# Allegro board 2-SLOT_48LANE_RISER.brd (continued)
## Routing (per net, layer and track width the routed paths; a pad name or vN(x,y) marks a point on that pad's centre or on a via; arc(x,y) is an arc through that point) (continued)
PE_CPU_RX_C_DN<12>: length 182
  TOP w0.089: 118.42,92.03 118.44,92.03 118.5,91.97 118.98,91.97 119.18,91.77 121.59,91.77 121.97,92.15 123.08,92.15 v5(123.29,92.36)
  TOP w0.135: 118.42,92.03 117.52,92.03 117.37,92.18 116.68,92.18 116.53,92.03 115.2,92.03 114.94,91.99 110.15,88.63 107.12,84.3 107.12,71.91 106.55,68.71 104.72,66.09 104.72,62.04 104.89,61.07 105.98,59.51 107.55,58.41 113.89,57.3 v8(120.37,50.82) 122.9,48.29 139.75,48.29 168.47,43.22 203.84,18.46 219.36,15.72 219.46,15.57 220.05,15.47 220.2,15.57 220.73,15.48 220.84,15.32 221.41,15.22 221.57,15.33 221.94,15.26 222.28,15.03 222.62,14.97 222.77,14.76 223.19,14.69 223.4,14.83 223.72,14.77 223.86,14.57 224.28,14.5 224.48,14.64 224.74,14.59 224.85,14.44 225.35,14.35 225.5,14.46 225.74,14.42 226.07,14.19 226.16,13.68 226.03,13.54 226.03,13.04 226.16,12.9 226.16,12.68 C99.1
  BOTTOM w0.135: U1.AB19 v5(123.29,92.36)
PE_CPU_RX_C_DN<13>: length 181.4
  TOP w0.089: v5(123.29,93.16) 123.05,92.93 121.78,92.93 121.63,92.78 120.09,92.78 119.65,93.22 119.01,93.22 118.95,93.28 118.93,93.28
  TOP w0.135: C100.1 222.17,12.69 222.17,12.88 221.99,13.06 221.99,13.25 222.18,13.43 222.18,13.62 221.97,13.78 221.28,13.9 221.12,13.78 220.59,13.88 220.47,14.04 219.94,14.14 219.79,14.03 219.24,14.12 219.13,14.28 218.79,14.34 218.4,14.61 217.01,14.86 216.86,14.75 216.29,14.85 216.19,15 215.66,15.09 215.48,14.97 214.95,15.06 214.83,15.24 214.3,15.33 214.17,15.24 213.56,15.35 213.47,15.48 203.19,17.29 167.98,41.95 139.1,47.04 v8(130,47.04) 122.15,47.04 114.93,54.26 112.01,56.31 106.74,57.23 104.87,58.55 103.78,60.09 103.52,61.61 103.52,67.03 105.41,69.73 105.92,72.62 105.92,84.6 106.05,85.28 108.73,89.11 114.69,93.28 118.93,93.28
  BOTTOM w0.124: U1.AB20 v5(123.29,93.16)
PE_CPU_RX_C_DN<14>: length 181.5
  TOP w0.089: 119.04,94.25 119.06,94.25 119.12,94.19 120.34,94.19 120.67,94.53 123.65,94.53 123.72,94.46 124.01,94.46 124.09,94.53 v5(124.09,94.76)
  TOP w0.135: 119.04,94.25 118.4,94.25 117.96,94.69 114.61,94.69 107.81,89.93 104.76,85.57 104.71,85.41 104.71,72.98 104.24,70.31 102.11,67.26 102.11,61.91 102.47,59.88 104.14,57.49 106.08,56.13 111.54,55.17 112.46,54.52 112.46,54.52 113.39,53.87 v8(119.79,47.47) 121.44,45.82 138.78,45.82 167.49,40.76 202.71,16.1 212.78,14.33 212.87,14.2 217.21,13.43 217.34,13.52 217.84,13.43 218.13,13.14 218.16,12.95 218.16,12.68 C101.1
  BOTTOM w0.135: U1.AB22 v5(124.09,94.76)
PE_CPU_RX_C_DN<15>: length 181.6
  TOP w0.089: v5(123.29,95.56) 123.51,95.56 123.59,95.47 123.59,95.22 123.49,95.12 119.94,95.12 119.48,95.57 119.48,95.65 119.47,95.67
  TOP w0.135: C102.1 214.15,11.91 214.15,12.3 213.77,12.56 211.75,12.92 211.54,13.23 202.2,14.87 166.86,39.61 139.42,44.45 121.01,44.45 v8(114.73,50.72) 112.78,52.68 110.78,54.08 105.38,55.03 102.94,56.74 101.1,59.37 100.91,60.44 100.91,67.69 103.05,70.75 103.51,73.36 103.51,86.07 103.56,86.13 106.9,90.89 114.1,95.93 114.41,95.99 119.15,95.99 119.47,95.67
  BOTTOM w0.135: U1.AB23 v5(123.29,95.56)
PE_CPU_RX_C_DP<0>: length 179.5
  TOP w0.089: 122.82,75.31 122.82,75.34 122.76,75.39 122.76,75.77 123.73,76.73 123.73,77.07 123.81,77.16 v5(124.09,77.16)
  TOP w0.135: C23.1 278.49,12.69 278.49,14.16 277.17,16.1 268.63,22.08 212.26,32.02 207.5,35.35 206.71,36.48 177.03,57.27 132.76,65.07 130.23,65.07 v8(125.86,69.44) 122.82,72.48 122.82,72.92 122.96,73.06 122.96,73.6 122.82,73.74 122.82,75.31 122.82,75.31
  BOTTOM w0.135: U1.AA1 v5(124.09,77.16)
PE_CPU_RX_C_DP<1>: length 179.7
  TOP w0.089: v5(124.09,77.96) 124.07,77.96 123.38,77.55 121.82,77.55 121.42,77.95 121.02,77.95 120.71,77.64 120.71,77.2
  TOP w0.135: C24.1 273.48,12.69 273.48,13.36 272.23,14.61 261.61,22.05 211.84,30.83 206.39,34.64 205.65,35.7 176.45,56.15 134.34,63.58 132.83,63.58 132.65,63.75 132.11,63.75 131.93,63.58 131.4,63.58 131.22,63.75 130.68,63.75 130.5,63.58 129.95,63.58 v8(122.39,71.13) 121.6,71.92 121.6,74.7 120.71,75.59 120.71,77.2
  BOTTOM w0.135: U1.AA2 v5(124.09,77.96)
PE_CPU_RX_C_DP<2>: length 179.3
  TOP w0.089: 120.3,78.73 120.32,78.74 120.32,78.82 120.67,79.17 123.53,79.17 v5(124.09,79.56)
  TOP w0.135: 120.3,78.73 120.3,78.65 119.69,78.03 119.69,75.21 119.99,74.9 119.99,71.81 v8(124.26,67.54) 129.67,62.13 130.3,62.13 130.43,62.26 131.02,62.26 131.14,62.13 131.68,62.13 131.78,62.23 132.42,62.23 132.53,62.13 135.09,62.13 175.64,54.98 204.77,34.61 205.35,33.78 211.14,29.72 257.3,21.59 257.42,21.54 257.42,21.54 262.47,19.44 268.47,15.24 269.43,13.87 269.48,13.59 269.48,12.69 C25.1
  BOTTOM w0.135: U1.AA4 v5(124.09,79.56)
PE_CPU_RX_C_DP<3>: length 178.6
  TOP w0.089: v5(124.09,80.36) 123.54,79.98 121,79.98 120.98,79.96
  TOP w0.135: 120.98,79.96 120.14,79.96 118.64,78.45 118.64,71.31 119.75,70.2 119.9,70.2 120.36,69.74 120.36,69.59 120.74,69.21 120.85,69.21 121.35,68.71 121.35,68.6 v8(122.03,67.92) 123.26,66.69 125.28,64.67 129.22,60.73 130.58,60.73 130.7,60.86 131.29,60.86 131.42,60.73 131.96,60.73 132.09,60.86 132.68,60.86 132.8,60.73 136.09,60.73 174.9,53.89 204.1,33.47 204.49,32.92 210.67,28.59 210.67,28.59 255.58,20.66 259.21,18.12 261.45,16.56 261.45,16.56 265.34,13.83 265.46,13.67 265.46,12.72 C26.1
  BOTTOM w0.135: U1.AA5 v5(124.09,80.36)
PE_CPU_RX_C_DP<4>: length 177.8
  TOP w0.089: v5(124.09,81.96) 123.55,81.58 121.39,81.58 120.96,82.01 120.38,82.01 120.32,81.95 120.3,81.95
  TOP w0.135: C79.1 259.46,12.71 259.46,14.05 258.27,15.76 255.64,17.59 247.91,20.8 210.2,27.44 173.92,52.84 136.65,59.41 133.25,59.41 133.15,59.51 132.51,59.51 132.41,59.41 131.87,59.41 131.8,59.49 131.11,59.49 131.03,59.41 128.66,59.41 v8(124.11,63.96) 121.29,66.78 121.29,66.93 120.91,67.31 120.76,67.31 120.22,67.85 120.22,67.96 120.22,68.03 119.81,68.44 119.73,68.44 119.63,68.44 119.25,68.82 119.25,69 118.85,69.4 118.77,69.4 118.67,69.4 117.44,70.63 117.44,79.66 118.38,80.99 119.62,81.86 120.16,81.95 120.3,81.95
  BOTTOM w0.135: U1.AA7 v5(124.09,81.96)
PE_CPU_RX_C_DP<5>: length 177.8
  TOP w0.089: 119.72,82.74 119.74,82.74 119.79,82.79 121.35,82.79 121.76,82.38 123.55,82.38 v5(124.09,82.76)
  TOP w0.135: C80.1 255.47,12.7 255.47,14.73 254.66,15.55 250.63,18.37 247.59,19.63 209.73,26.31 173.45,51.7 137.15,58.1 131.04,58.1 130.93,58.21 130.29,58.21 130.18,58.1 129.64,58.1 129.53,58.21 128.9,58.21 128.79,58.1 128.03,58.1 v8(120.69,65.44) 118.79,67.34 118.79,67.52 118.39,67.92 118.21,67.92 117.83,68.31 117.83,68.48 117.42,68.89 117.24,68.89 116.23,69.9 116.23,79.89 116.29,80.19 116.49,80.49 117.53,81.97 118.47,82.63 119.09,82.74 119.72,82.74
  BOTTOM w0.135: U1.AA8 v5(124.09,82.76)
PE_CPU_RX_C_DP<6>: length 177.7
  TOP w0.089: v5(124.09,84.36) 123.7,84.09 123.24,83.94 122.04,83.94 121.92,83.81 121.36,83.81 121.16,84.02 119.42,84.02 119.36,83.97
  TOP w0.135: C81.1 251.53,12.65 251.53,12.85 251.36,13.78 251.36,13.79 251.08,15.38 250.52,16.18 247.25,18.47 209.13,25.19 172.91,50.58 137.16,56.88 127.33,56.88 123.81,60.41 v8(122.23,61.99) 118.22,66 118.22,66.11 118.22,66.19 117.81,66.59 117.62,66.59 117.24,66.98 117.24,67.16 116.83,67.57 116.65,67.57 116.27,67.95 116.27,68.12 115.84,68.55 115.67,68.55 115.03,69.18 115.03,80.51 116.49,82.59 116.65,82.82 118.22,83.91 118.37,83.94 118.36,83.94 118.51,83.97 119.36,83.97
  BOTTOM w0.135: U1.AA10 v5(124.09,84.36)
PE_CPU_RX_C_DP<7>: length 177.5
  TOP w0.089: 118.88,85.14 118.9,85.14 118.96,85.19 120.04,85.19 120.49,84.75 123.28,84.75 123.29,84.76 123.39,84.79 123.66,84.91 124.08,85.16 v5(124.09,85.16)
  TOP w0.135: 118.88,85.14 117.75,85.14 117.25,85.05 116.49,84.52 115.5,83.82 113.89,81.52 113.83,81.22 113.83,68.33 114.42,67.75 114.58,67.75 115.01,67.31 115.01,67.15 115.39,66.77 115.55,66.77 115.98,66.34 115.98,66.18 v8(119.52,62.64) 126.63,55.53 127.92,55.53 127.99,55.61 127.99,55.61 128.07,55.68 128.6,55.68 128.68,55.61 128.68,55.61 128.75,55.53 129.29,55.53 129.36,55.61 129.36,55.61 129.44,55.68 129.98,55.68 130.05,55.61 130.05,55.61 130.12,55.53 137.68,55.53 172.45,49.4 208.67,24.05 239.69,18.58 244.52,16.58 247.04,14.81 247.47,14.19 247.47,12.7 C82.1
  BOTTOM w0.135: U1.AA11 v5(124.09,85.16)
PE_CPU_RX_C_DP<8>: length 176.8
  TOP w0.089: 118.42,86.34 118.44,86.34 118.5,86.39 118.88,86.39 119.43,86.94 123.21,86.94 v5(124.09,87.56)
  TOP w0.135: 118.42,86.34 117.08,86.34 116.61,86.14 116.49,86.06 114.7,84.8 112.63,81.85 112.63,67.78 115.4,65.01 115.4,64.61 116.18,63.84 116.28,63.84 116.78,63.33 116.78,63.23 117.17,62.85 117.29,62.85 117.77,62.36 117.77,62.24 v8(120.78,59.23) 125.81,54.2 127.87,54.2 128,54.33 128.64,54.33 128.77,54.2 129.31,54.2 129.44,54.33 130.08,54.33 130.21,54.2 138.32,54.2 171.98,48.27 208.2,22.91 236.56,17.91 239.57,16.66 242.24,14.8 242.47,14.14 242.47,12.7 C83.1
  BOTTOM w0.135: U1.AA13 v5(124.09,87.56)
PE_CPU_RX_C_DP<9>: length 176.8
  TOP w0.089: v5(124.09,88.36) 123.51,87.96 122.29,87.96 122.05,87.72 118.96,87.72 118.93,87.69
  TOP w0.135: 118.93,87.69 117.52,87.69 116.49,87.51 116.31,87.47 113.91,85.79 112.5,84.38 111.5,82.95 111.43,82.55 111.43,67.28 113.59,65.12 113.59,64.49 114.33,63.75 114.53,63.75 114.96,63.32 114.96,63.12 115.34,62.74 115.55,62.74 115.98,62.3 115.98,62.1 116.36,61.72 116.56,61.72 117,61.29 117,61.08 v8(117.9,60.19) 125.3,52.78 139.44,52.78 171.4,47.15 207.61,21.8 235.88,16.81 237.32,15.8 238.48,14.14 238.48,12.69 C84.1
  BOTTOM w0.135: U1.AA14 v5(124.09,88.36)
PE_CPU_RX_C_DP<10>: length 180.1
  TOP w0.089: v5(124.09,89.96) 123.69,89.56 122.97,89.56 122.62,89.2 119.69,89.2 119.43,88.95 118.88,88.95 118.82,88.89 118.8,88.89
  TOP w0.135: 118.8,88.89 116.87,88.89 116.49,88.83 115.95,88.73 112.95,86.63 111.09,84.77 110.73,84.26 110.23,83.05 110.23,66.78 112.19,64.82 112.19,63.63 112.89,62.93 113.04,62.93 113.47,62.5 113.47,62.35 113.85,61.97 114,61.97 114.44,61.54 114.44,61.38 v8(119.6,56.22) 124.44,51.38 125.67,51.38 125.79,51.51 126.38,51.51 126.51,51.38 127.05,51.38 127.15,51.49 127.79,51.49 127.89,51.38 140.44,51.38 170.72,46.05 173.81,43.88 173.95,43.13 174.18,42.97 174.93,43.1 175.37,42.79 175.5,42.04 175.73,41.88 176.48,42.01 176.92,41.7 177.05,40.95 177.28,40.79 178.03,40.92 178.47,40.61 178.6,39.87 178.84,39.7 179.59,39.84 180.03,39.53 180.16,38.78 180.39,38.62 181.14,38.75 182.25,37.97 182.35,37.38 182.94,36.97 183.53,37.07 184.33,36.52 184.43,35.93 185.02,35.51 185.61,35.62 206.93,20.69 227.12,17.13 230.69,16.5 231.22,16.13 233.29,15.77 233.89,15.35 234.47,14.52 234.47,12.7 C85.1
  BOTTOM w0.135: U1.AA16 v5(124.09,89.96)
PE_CPU_RX_C_DP<11>: length 182.4
  TOP w0.089: v5(124.09,90.76) 123.69,90.36 122.89,90.36 122.53,90.01 119.88,90.01 119.46,90.42 118.93,90.42 118.87,90.37 118.85,90.37
  TOP w0.135: 118.85,90.37 118.85,90.37 116.5,90.37 116.49,90.37 115.93,90.27 110.89,86.74 109.69,85.02 109.69,85.02 108.62,83.08 108.62,71.31 108.03,67.97 106.22,65.39 106.22,62.31 106.26,62.11 106.94,61.14 108.65,59.95 109.67,59.76 109.83,59.88 110.36,59.78 110.48,59.62 111.91,59.37 112.05,59.47 112.62,59.37 112.72,59.23 114.67,58.88 115.92,57.64 116.1,57.64 116.51,57.23 116.51,57.05 v8(118.28,55.28) 123.57,49.99 128.67,49.99 128.82,50.14 129.36,50.14 129.52,49.99 130.31,49.99 130.47,50.14 131.01,50.14 131.16,49.99 140.29,49.99 169.23,44.88 184.69,34.06 205.05,19.8 224.16,16.41 226.67,15.96 227.15,15.63 227.63,15.29 229.9,15.29 230.51,14.68 230.51,12.67 C86.1
  BOTTOM w0.135: U1.AA17 v5(124.09,90.76)
PE_CPU_RX_C_DP<12>: length 182.2
  TOP w0.089: 118.42,91.73 118.44,91.73 118.5,91.78 118.9,91.78 119.1,91.58 121.67,91.58 122.05,91.96 123.69,91.96 v5(124.09,92.36)
  TOP w0.135: C87.1 226.47,12.7 226.47,13.7 226.35,14.36 225.86,14.7 222.4,15.32 222.06,15.55 203.96,18.74 168.59,43.51 139.77,48.59 126.18,48.59 126,48.77 125.54,48.77 125.36,48.59 124.89,48.59 124.72,48.77 124.25,48.77 124.07,48.59 123.03,48.59 v8(119.47,52.15) 116.73,54.89 116.73,55.13 116.35,55.51 116.11,55.51 115.73,55.89 115.73,56.13 115.35,56.51 115.11,56.51 114.04,57.58 107.67,58.7 106.2,59.73 105.18,61.19 105.02,62.07 105.02,65.99 106.84,68.59 107.42,71.88 107.42,84.2 110.37,88.41 115.06,91.7 115.22,91.73 118.42,91.73
  BOTTOM w0.135: U1.AA19 v5(124.09,92.36)
PE_CPU_RX_C_DP<13>: length 181.5
  TOP w0.089: 118.93,92.97 118.95,92.97 119.01,93.03 119.57,93.03 120.01,92.59 121.71,92.59 121.86,92.74 123.66,92.74 v5(124.09,93.16)
  TOP w0.135: C88.1 222.48,12.69 222.48,13.77 222.09,14.07 218.91,14.63 218.52,14.9 203.31,17.58 168.21,42.16 168.1,42.24 139.13,47.35 v8(127.79,47.35) 122.28,47.35 121.49,48.13 121.49,48.26 120.98,48.77 120.86,48.77 120.26,49.36 120.26,49.47 120.26,49.56 119.86,49.97 119.65,49.97 118.86,50.76 118.86,50.94 118.45,51.35 118.27,51.35 117.05,52.58 117.05,52.69 117.05,52.78 116.64,53.18 116.44,53.18 115.13,54.49 112.13,56.59 106.86,57.52 105.08,58.77 104.07,60.21 103.82,61.63 103.82,66.93 105.69,69.61 106.22,72.59 106.22,84.48 106.34,85.16 108.95,88.89 114.78,92.97 118.93,92.97
  BOTTOM w0.135: U1.AA20 v5(124.09,93.16)
PE_CPU_RX_C_DP<14>: length 181.4
  TOP w0.089: v5(124.09,93.96) 124.09,94.17 123.99,94.27 123.64,94.27 123.57,94.34 120.75,94.34 120.42,94 119.12,94 119.06,93.94 119.04,93.94
  TOP w0.135: 119.04,93.94 118.28,93.94 117.83,94.39 114.71,94.39 108.03,89.71 105.05,85.45 105.02,85.28 105.02,72.95 104.53,70.19 102.41,67.17 102.41,61.93 102.76,60 104.36,57.71 106.2,56.42 111.66,55.46 113.1,54.45 113.58,54.11 113.6,54.09 114.64,53.05 114.74,53.05 114.84,53.05 115.22,52.67 115.22,52.57 115.22,52.47 115.6,52.09 115.78,52.09 116.19,51.68 116.19,51.51 116.57,51.13 116.75,51.13 117.15,50.72 117.15,50.54 117.57,50.13 117.67,50.13 118.18,49.62 118.18,49.52 v8(118.81,48.88) 121.57,46.13 138.81,46.13 167.61,41.05 202.83,16.39 212.95,14.6 213.05,14.47 217.13,13.75 217.26,13.84 217.98,13.72 218.41,13.29 218.47,12.98 218.47,12.71 C89.1
  BOTTOM w0.135: U1.AA22 v5(124.09,93.96)
PE_CPU_RX_C_DP<15>: length 181.7
  TOP w0.089: v5(124.09,95.56) 123.87,95.56 123.78,95.47 123.78,95.14 123.57,94.93 119.86,94.93 119.35,95.44 119.27,95.44 119.25,95.45
  TOP w0.135: C90.1 214.45,11.96 214.45,12.46 213.89,12.85 211.93,13.2 211.71,13.5 202.32,15.16 166.98,39.9 139.44,44.75 128,44.75 127.9,44.86 127.06,44.86 126.96,44.75 126.42,44.75 126.32,44.86 125.47,44.86 125.37,44.75 124.83,44.75 124.73,44.86 123.89,44.86 123.79,44.75 123.25,44.75 123.12,44.88 122.33,44.88 122.2,44.75 121.13,44.75 v8(114,51.89) 112.97,52.92 110.9,54.37 105.5,55.32 103.16,56.96 101.38,59.49 101.21,60.46 101.21,67.59 103.34,70.63 103.82,73.33 103.82,85.96 103.82,85.96 107.12,90.67 114.22,95.64 114.44,95.68 119.02,95.68 119.25,95.45
  BOTTOM w0.135: U1.AA23 124.49,95.16 v5(124.09,95.56)
PE_CPU_RX_DN<0>: length 8.3
  TOP w0.135: C35.2 278.17,11.18 278.17,6.15 277.83,5.8 J5.A17
PE_CPU_RX_DN<1>: length 8.3
  TOP w0.135: C36.2 273.17,11.18 273.17,6.15 272.83,5.8 J5.A22
PE_CPU_RX_DN<2>: length 8.3
  TOP w0.135: J5.A26 268.83,5.8 269.19,6.16 269.19,11.17 C37.2
PE_CPU_RX_DN<3>: length 8.3
  TOP w0.135: C38.2 265.17,11.18 265.17,6.15 264.83,5.8 J5.A30
PE_CPU_RX_DN<4>: length 8.3
  TOP w0.135: C91.2 259.17,11.18 259.17,6.15 258.83,5.8 J5.A36
PE_CPU_RX_DN<5>: length 8.3
  TOP w0.135: C92.2 255.17,11.18 255.17,6.15 254.83,5.8 J5.A40
PE_CPU_RX_DN<6>: length 8.4
  TOP w0.135: C93.2 251.17,11.18 251.17,10.1 251.06,9.98 251.06,9.39 251.17,9.28 251.17,6.15 250.83,5.8 J5.A44
PE_CPU_RX_DN<7>: length 8.3
  TOP w0.135: C94.2 247.17,11.18 247.17,6.15 246.83,5.8 J5.A48
PE_CPU_RX_DN<8>: length 8.3
  TOP w0.135: C95.2 242.17,11.18 242.17,6.15 241.83,5.8 J5.A53
PE_CPU_RX_DN<9>: length 8.3
  TOP w0.135: J5.A57 237.83,5.8 238.17,6.15 238.17,11.18 C96.2
PE_CPU_RX_DN<10>: length 8.3
  TOP w0.135: J5.A61 233.83,5.8 234.17,6.15 234.17,11.18 C97.2
PE_CPU_RX_DN<11>: length 8.3
  TOP w0.135: C98.2 230.17,11.18 230.17,6.15 229.83,5.8 J5.A65
PE_CPU_RX_DN<12>: length 8.3
  TOP w0.135: J5.A69 225.83,5.8 226.17,6.15 226.17,11.18 C99.2
PE_CPU_RX_DN<13>: length 8.3
  TOP w0.135: J5.A73 221.83,5.8 222.17,6.15 222.17,11.18 C100.2
PE_CPU_RX_DN<14>: length 8.3
  TOP w0.135: C101.2 218.17,11.18 218.17,6.15 217.83,5.8 J5.A77
PE_CPU_RX_DN<15>: length 7.5
  TOP w0.135: J5.A81 213.83,5.8 214.17,6.15 214.17,10.42 C102.2
PE_CPU_RX_DP<0>: length 8.3
  TOP w0.135: C23.2 278.48,11.18 278.48,6.15 278.83,5.8 J5.A16
PE_CPU_RX_DP<1>: length 8.3
  TOP w0.135: C24.2 273.48,11.18 273.48,6.15 273.83,5.8 J5.A21
PE_CPU_RX_DP<2>: length 8.4
  TOP w0.135: C25.2 269.5,11.2 269.5,8.5 269.65,8.35 269.65,7.81 269.5,7.66 269.5,6.13 269.83,5.8 J5.A25
PE_CPU_RX_DP<3>: length 8.3
  TOP w0.135: C26.2 265.48,11.18 265.48,6.15 265.83,5.8 J5.A29
PE_CPU_RX_DP<4>: length 8.3
  TOP w0.135: C79.2 259.48,11.18 259.48,6.15 259.83,5.8 J5.A35
PE_CPU_RX_DP<5>: length 8.3
  TOP w0.135: J5.A39 255.83,5.8 255.48,6.15 255.48,11.18 C80.2
PE_CPU_RX_DP<6>: length 8.3
  TOP w0.135: C81.2 251.48,11.18 251.48,6.15 251.83,5.8 J5.A43
PE_CPU_RX_DP<7>: length 8.3
  TOP w0.135: C82.2 247.48,11.18 247.48,6.15 247.83,5.8 J5.A47
PE_CPU_RX_DP<8>: length 8.3
  TOP w0.135: J5.A52 242.83,5.8 242.48,6.15 242.48,11.18 C83.2
PE_CPU_RX_DP<9>: length 8.3
  TOP w0.135: C84.2 238.48,11.18 238.48,6.15 238.83,5.8 J5.A56
PE_CPU_RX_DP<10>: length 8.3
  TOP w0.135: J5.A60 234.83,5.8 234.48,6.15 234.48,11.18 C85.2
PE_CPU_RX_DP<11>: length 8.3
  TOP w0.135: C86.2 230.48,11.18 230.48,6.15 230.83,5.8 J5.A64
PE_CPU_RX_DP<12>: length 8.3
  TOP w0.135: J5.A68 226.83,5.8 226.48,6.15 226.48,11.18 C87.2
PE_CPU_RX_DP<13>: length 8.3
  TOP w0.135: C88.2 222.48,11.18 222.48,6.15 222.83,5.8 J5.A72
PE_CPU_RX_DP<14>: length 8.3
  TOP w0.135: J5.A76 218.83,5.8 218.48,6.15 218.48,11.18 C89.2
PE_CPU_RX_DP<15>: length 7.5
  TOP w0.135: J5.A80 214.83,5.8 214.48,6.15 214.48,10.42 C90.2
PE_CPU_TX_DN<0>: length 190.5
  BOTTOM w0.135: J5.B15 279.83,5.8 280.17,6.15 280.17,9.3 279.31,14.21 277.99,15.52 277.37,15.96 277.35,15.96 277.29,16.01 277.27,16.03 269.22,21.67 269.17,21.68 212.14,31.73 209.71,33.43 207.28,35.13 203.4,40.68 181.2,56.22 139.18,63.63 v8(134.42,63.63) 130.25,63.63 122.52,71.36 122.52,74.78 121.61,75.69 121.61,77.24 U1.AE1
PE_CPU_TX_DN<1>: length 191.3
  BOTTOM w0.089: U1.AE2 121.11,78.18 120.98,78.18 120.52,77.72 120.52,77.31 120.43,77.22 120.42,77.22 120.41,77.21 120.41,77.2
  BOTTOM w0.135: 120.41,77.2 120.41,75.47 121.3,74.58 121.3,73.9 121.16,73.76 121.16,73.22 121.3,73.08 121.3,70.87 129.68,62.48 129.7,62.48 129.75,62.43 v8(130.46,62.43) 138.65,62.43 180.81,55 202.31,39.95 206.16,34.45 211.68,30.58 212.1,30.47 260.45,21.94 264.14,19.36 264.58,19.44 265,20.05 265.19,20.08 265.7,19.72 265.74,19.53 265.31,18.93 265.39,18.49 266.11,17.98 266.54,18.06 266.97,18.67 267.16,18.7 267.67,18.34 267.71,18.16 267.28,17.55 267.36,17.11 268.82,16.09 271.57,14.16 271.57,14.16 272.29,13.65 272.33,13.44 272.66,13.21 272.87,13.25 273.21,13.02 273.24,12.8 273.57,12.57 273.79,12.61 274.4,12.18 275,11.33 275.17,10.33 275.17,6.15 274.83,5.8 J5.B20
PE_CPU_TX_DN<2>: length 187.6
  BOTTOM w0.089: 120.03,79.05 120.12,79.15 120.13,79.15 120.59,79.61 120.77,79.79 121.11,79.79 U1.AE4 ; 119.21,77.5 119.21,77.47
  BOTTOM w0.135: J5.B24 270.83,5.8 271.17,6.15 271.17,10.24 271,11.22 270.45,12 269.95,12.35 269.74,12.32 269.41,12.55 269.37,12.76 269.04,12.99 268.83,12.96 268.5,13.19 268.46,13.4 257.18,21.3 211.02,29.44 205.13,33.56 201.09,39.33 180.34,53.84 139,61.13 v8(131.65,61.13) 129.23,61.13 120.3,70.05 119.69,70.67 119.69,72.84 119.53,72.99 119.53,73.53 119.69,73.69 119.69,74.78 119.21,75.26 119.21,77.47 ; 119.21,77.5 119.21,78.23 120.03,79.05
PE_CPU_TX_DN<3>: length 187.1
  BOTTOM w0.089: 120.12,80.64 120.14,80.64 120.2,80.58 121.11,80.58 U1.AE5
  BOTTOM w0.135: 120.12,80.64 119.88,80.64 119.44,80.56 118.47,79.88 118.33,79.19 118.33,70.2 128.6,59.93 v8(133.22,59.93) 138.89,59.93 179.87,52.7 200.23,38.46 204.27,32.7 210.55,28.3 254.05,20.62 264.26,13.48 264.3,13.26 264.63,13.03 264.84,13.07 265.18,12.84 265.21,12.62 265.54,12.39 265.76,12.43 266.36,12.01 267.01,11.08 267.17,10.14 267.17,6.15 266.83,5.8 J5.B28
PE_CPU_TX_DN<4>: length 184.9
  BOTTOM w0.089: 120.3,82.26 120.32,82.26 120.38,82.2 121.13,82.2 U1.AE7
  BOTTOM w0.135: 120.3,82.26 120.14,82.26 119.5,82.15 118.16,81.21 117.13,79.76 117.13,77.46 116.99,77.32 116.99,76.68 117.13,76.55 117.13,69.7 128.1,58.73 v8(129.21,58.73) 138.78,58.73 179.4,51.57 199.31,37.63 203.34,31.88 210.08,27.16 247.83,20.5 258.56,12.99 258.59,12.81 258.95,12.55 259.13,12.58 259.47,12.35 259.51,12.14 259.84,11.91 260.05,11.94 260.52,11.61 260.98,10.95 261.17,9.86 261.17,6.15 260.83,5.8 J5.B34
PE_CPU_TX_DN<5>: length 184.4
  BOTTOM w0.089: 119.72,83.04 119.74,83.04 119.79,82.98 121.11,82.98 U1.AE8
  BOTTOM w0.135: 119.72,83.04 119.04,83.04 119.03,83.04 118.35,82.92 117.31,82.19 116.49,81.02 116,80.31 115.93,79.91 115.93,69.2 127.6,57.53 v8(128.35,57.53) 138.68,57.53 158.81,53.98 178.93,50.43 198.45,36.77 202.47,31.02 209.61,26.02 244.75,19.82 252.15,14.64 254.62,12.91 254.65,12.7 254.99,12.47 255.2,12.51 255.53,12.27 255.57,12.06 255.9,11.83 256.11,11.87 256.44,11.64 256.98,10.87 257.17,9.76 257.17,6.15 256.83,5.8 J5.B38
PE_CPU_TX_DN<6>: length 184.2
  BOTTOM w0.089: 119.36,84.27 119.38,84.27 119.44,84.21 119.96,84.21 120.35,84.6 121.13,84.6 U1.AE10
  BOTTOM w0.135: J5.B42 252.83,5.8 253.17,6.15 253.17,9.86 253.01,10.77 252.46,11.56 251.97,11.9 251.76,11.87 251.43,12.1 251.39,12.31 251.06,12.54 250.85,12.5 250.51,12.74 250.48,12.95 241.62,19.15 209.02,24.9 201.67,30.07 197.59,35.9 178.46,49.29 138.57,56.32 v8(129.77,56.32) 127.11,56.32 114.73,68.7 114.73,80.6 116.43,83.04 116.49,83.08 118.1,84.2 118.49,84.27 119.36,84.27
PE_CPU_TX_DN<7>: length 184.1
  BOTTOM w0.089: U1.AE11 121.11,85.38 118.96,85.38 118.9,85.44 118.88,85.44
  BOTTOM w0.135: 118.88,85.44 117.7,85.44 117.7,85.44 117.13,85.34 116.49,84.89 115.28,84.04 113.6,81.64 113.53,81.24 113.53,68.2 126.61,55.12 v8(130.96,55.12) 138.26,55.12 178.05,48.11 196.72,35.04 200.84,29.16 208.55,23.76 238.78,18.43 246.53,13.01 246.57,12.79 246.9,12.56 247.11,12.6 247.44,12.37 247.48,12.15 247.81,11.92 248.03,11.96 248.61,11.55 249.06,10.91 249.17,10.27 249.17,6.15 248.83,5.8 J5.B46
PE_CPU_TX_DN<8>: length 183
  BOTTOM w0.089: 118.42,86.64 118.44,86.64 118.5,86.58 118.8,86.58 119.23,87.01 121.14,87.01 U1.AE13
  BOTTOM w0.135: 118.42,86.64 117.02,86.64 116.49,86.42 116.46,86.41 114.48,85.02 112.33,81.95 112.33,67.65 126.06,53.92 v8(129.14,53.92) 138.15,53.92 177.58,46.97 195.86,34.17 199.97,28.3 208.08,22.62 234.41,17.98 241.48,13.03 241.52,12.82 241.85,12.58 242.06,12.62 242.39,12.39 242.43,12.18 242.76,11.94 242.98,11.98 243.42,11.67 243.95,10.92 244.17,9.64 244.17,6.15 243.83,5.8 J5.B51
PE_CPU_TX_DN<9>: length 182.9
  BOTTOM w0.089: 118.93,87.99 118.95,87.99 119.01,87.93 119.46,87.93 119.61,87.78 121.11,87.78 U1.AE14
  BOTTOM w0.135: 118.93,87.99 117.49,87.99 116.49,87.82 116.19,87.76 113.72,86.03 112.26,84.58 111.21,83.07 111.12,82.57 111.12,67.16 125.56,52.72 v8(126.21,52.72) 138.03,52.72 177.11,45.83 195,33.31 199.11,27.44 207.61,21.49 231.31,17.31 234.05,15.39 236.78,13.48 236.82,13.27 237.15,13.03 237.37,13.07 237.7,12.84 237.73,12.63 238.07,12.39 238.28,12.43 238.61,12.2 238.65,11.99 238.98,11.76 239.19,11.79 239.64,11.48 239.85,11.18 240.06,10.87 240.17,10.25 240.17,6.15 239.83,5.8 J5.B55
PE_CPU_TX_DN<10>: length 186.7
  BOTTOM w0.089: 118.8,89.2 118.82,89.2 118.88,89.14 119.35,89.14 119.65,89.44 121.17,89.44 U1.AE16
  BOTTOM w0.135: J5.B59 235.83,5.8 236.17,6.15 236.17,9.6 235.95,10.86 235.38,11.67 234.48,12.3 234.27,12.27 233.94,12.5 233.9,12.71 233.57,12.94 233.36,12.91 233.03,13.14 232.99,13.35 231.82,14.17 231.56,14.12 231.45,13.96 230.94,13.87 230.51,14.17 230.42,14.68 230.54,14.84 230.49,15.1 230.27,15.25 230.01,15.21 229.9,15.05 229.39,14.96 228.96,15.26 228.87,15.77 228.98,15.93 228.94,16.19 228.33,16.61 207.13,20.35 198.25,26.57 194.14,32.44 176.64,44.69 137.95,51.51 v8(127.36,51.51) 125.07,51.51 115.74,60.84 115.61,60.84 115.48,60.84 115.2,60.56 114.68,60.56 114.31,60.92 114.31,61.44 114.59,61.72 114.59,61.99 114.4,62.18 114.14,62.18 113.86,61.9 113.34,61.9 112.97,62.27 112.97,62.78 113.25,63.06 113.25,63.33 109.92,66.66 109.92,83.11 110.46,84.41 110.85,84.97 112.75,86.86 115.83,89.02 116.49,89.14 116.85,89.2 118.8,89.2
PE_CPU_TX_DN<11>: length 188.2
  BOTTOM w0.089: U1.AE17 121.11,90.18 119.97,90.18 119.54,90.61 118.93,90.61 118.87,90.67
  BOTTOM w0.135: J5.B63 231.83,5.8 232.17,6.15 232.17,10.23 232.09,10.7 231.73,11.21 231.22,11.57 227.97,13.84 227.77,13.8 227.36,14.09 227.33,14.29 226.92,14.58 226.66,14.58 226.31,14.83 226.27,15.03 226.09,15.16 225.32,15.7 224.95,15.96 224.55,16.03 224.55,16.03 206.21,19.26 197.15,25.61 192.83,31.78 175.96,43.59 140.84,49.78 v8(128.5,49.78) 124.99,49.78 116.41,58.36 115.79,58.79 107.73,60.21 106.72,60.92 106.02,61.92 105.92,62.48 105.92,65.49 107.75,68.09 108.32,71.34 108.32,83.16 109.42,85.17 109.43,85.18 110.67,86.96 114.31,89.5 114.34,89.71 114.75,89.99 114.95,89.96 115.81,90.56 116.44,90.67 116.47,90.67 118.87,90.67 118.87,90.67
PE_CPU_TX_DN<12>: length 188.5
  BOTTOM w0.089: 118.42,92.03 118.44,92.03 118.5,91.97 118.98,91.97 119.24,91.71 121.04,91.71 U1.AE19
  BOTTOM w0.135: J5.B67 227.83,5.8 228.17,6.15 228.17,7.24 228.17,9.89 227.97,11.04 227.8,11.29 227.62,11.53 222.42,15.18 205.75,18.12 196.29,24.75 191.97,30.91 175.59,42.38 140.44,48.58 v8(127.28,48.58) 122.76,48.58 114.5,56.85 113.26,57.71 112.81,57.81 106.93,58.84 105.98,59.51 104.88,61.09 104.72,61.98 104.72,66.09 106.55,68.71 107.12,71.91 107.12,84.3 108.51,86.29 108.48,86.47 108.91,87.08 109.09,87.11 110.15,88.63 114.94,91.99 115.2,92.03 116.53,92.03 116.68,92.18 117.37,92.18 117.52,92.03 118.42,92.03
PE_CPU_TX_DN<13>: length 188.3
  BOTTOM w0.089: U1.AE20 121.11,92.58 119.94,92.58 119.3,93.22 119.01,93.22 118.95,93.28 118.93,93.28
  BOTTOM w0.135: J5.B71 223.83,5.8 224.17,6.15 224.17,9.92 224.11,10.27 224.05,10.62 223.42,11.51 219.2,14.47 205.39,16.91 195.08,24.12 190.76,30.29 175.11,41.25 140.33,47.38 v8(126.11,47.38) 122.26,47.38 116.35,53.3 116.12,53.3 115.67,53.75 115.67,53.97 114.38,55.26 112.68,56.46 106.49,57.55 105.1,58.52 103.71,60.5 103.52,61.61 103.52,67.03 105.41,69.73 105.92,72.62 105.92,84.6 106.05,85.28 108.73,89.11 114.69,93.28 115.75,93.28 115.82,93.35 115.89,93.42 116.54,93.42 116.61,93.35 116.68,93.28 118.93,93.28
PE_CPU_TX_DN<14>: length 188.5
  BOTTOM w0.089: U1.AE22 121.13,94.2 118.98,94.2 118.92,94.26 118.9,94.26
  BOTTOM w0.135: J5.B75 219.83,5.8 220.17,6.15 220.17,8.11 220.02,8.26 220.02,8.96 220.17,9.11 220.17,10.26 220.06,10.9 219.71,11.4 218.08,12.55 217.87,12.51 217.35,12.88 217.31,13.08 216.35,13.75 204.77,15.79 194.32,23.11 189.9,29.43 174.64,40.11 140.95,46.05 v8(125.3,46.05) 121.21,46.05 113.39,53.87 112.46,54.52 112.46,54.52 111.54,55.17 106.08,56.13 104.14,57.49 102.47,59.88 102.11,61.91 102.11,67.26 104.24,70.31 104.71,72.98 104.71,85.41 104.76,85.57 107.81,89.93 114.61,94.69 116,94.69 116.07,94.77 116.87,94.77 116.94,94.69 117.96,94.69 118.39,94.26 118.9,94.26
PE_CPU_TX_DN<15>: length 188.2
  BOTTOM w0.089: 119.47,95.67 119.48,95.65 119.48,95.57 120.07,94.98 121.11,94.98 U1.AE23
  BOTTOM w0.135: J5.B79 215.83,5.54 216.17,5.89 216.17,7.91 216.08,8 216.08,8.75 216.17,8.84 216.17,9.74 216.01,10.69 215.63,11.23 212.9,13.14 204.28,14.66 190.97,23.98 187.41,29.06 172.94,39.19 140.84,44.85 v8(122.2,44.85) 120.61,44.85 112.78,52.68 110.78,54.08 105.38,55.03 102.94,56.74 101.1,59.37 100.91,60.44 100.91,67.69 103.05,70.75 103.51,73.36 103.51,86.07 103.58,86.15 106.9,90.89 114.1,95.93 114.41,95.99 116.45,95.99 116.55,96.09 117.3,96.09 117.4,95.99 119.15,95.99 119.47,95.67
PE_CPU_TX_DP<0>: length 190.5
  BOTTOM w0.135: J5.B14 280.83,5.8 280.48,6.15 280.48,9.33 279.59,14.35 278.19,15.76 277.47,16.26 277.44,16.28 277.07,16.54 276.64,16.85 276.55,16.9 276.53,16.92 269.4,21.92 269.31,21.98 269.22,21.98 212.26,32.02 207.5,35.35 203.62,40.89 181.32,56.51 139.2,63.94 v8(131.47,63.94) 130.37,63.94 122.82,71.49 122.82,72.92 122.96,73.06 122.96,73.6 122.82,73.74 122.82,74.91 121.91,75.82 121.91,77.39 U1.AD1
PE_CPU_TX_DP<1>: length 191.4
  BOTTOM w0.089: U1.AD2 121.87,78.36 121.5,77.99 121.06,77.99 120.71,77.64 120.71,77.2
  BOTTOM w0.135: 120.71,77.2 120.71,75.59 121.6,74.7 121.6,71 129.81,62.79 129.83,62.79 129.88,62.74 v8(132.74,62.74) 138.68,62.74 180.93,55.29 202.53,40.17 206.38,34.67 211.81,30.86 212.16,30.77 260.57,22.23 264.21,19.69 264.4,19.72 264.82,20.33 265.26,20.41 265.98,19.9 266.06,19.46 265.63,18.85 265.67,18.67 266.18,18.31 266.37,18.34 266.79,18.95 267.23,19.03 267.95,18.52 268.03,18.08 267.6,17.47 267.64,17.29 269,16.34 269.79,15.78 274.62,12.39 275.29,11.45 275.48,10.36 275.48,6.15 275.83,5.8 J5.B19
PE_CPU_TX_DP<2>: length 187.7
  BOTTOM w0.089: 120.25,78.91 120.26,78.93 120.26,79.01 120.85,79.6 121.57,79.6 U1.AD4 ; 119.51,77.5 119.51,77.47
  BOTTOM w0.135: 120.25,78.91 120.25,78.84 119.51,78.1 119.51,77.5 ; 119.51,77.47 119.51,75.39 119.99,74.9 119.99,70.79 129.35,61.43 v8(133.96,61.43) 139.02,61.43 180.46,54.13 201.31,39.55 205.35,33.78 211.14,29.72 257.3,21.59 270.67,12.22 271.29,11.34 271.48,10.26 271.48,6.15 271.83,5.8 J5.B23
PE_CPU_TX_DP<3>: length 187.2
  BOTTOM w0.089: 120.12,80.34 120.25,80.34 120.3,80.39 121.56,80.39 U1.AD5
  BOTTOM w0.135: J5.B27 267.83,5.8 267.48,6.15 267.48,10.16 267.3,11.2 266.58,12.23 254.17,20.91 210.67,28.59 204.49,32.92 200.45,38.68 179.99,52.99 138.92,60.23 v8(130.2,60.23) 128.73,60.23 118.64,70.32 118.64,79.06 118.75,79.71 119.56,80.27 119.91,80.34 120.12,80.34
PE_CPU_TX_DP<4>: length 184.9
  BOTTOM w0.089: U1.AD7 121.87,82.36 121.52,82.01 120.38,82.01 120.32,81.95 120.3,81.95
  BOTTOM w0.135: J5.B33 261.83,5.8 261.48,6.15 261.48,9.89 261.27,11.07 260.74,11.83 247.95,20.79 210.2,27.44 203.56,32.1 199.53,37.85 179.52,51.85 138.81,59.03 v8(131.78,59.03) 128.23,59.03 117.44,69.82 117.44,79.66 118.38,80.99 119.62,81.86 120.16,81.95 120.3,81.95
PE_CPU_TX_DP<5>: length 184.5
  BOTTOM w0.089: U1.AD8 121.56,82.79 119.79,82.79 119.74,82.74 119.72,82.74
  BOTTOM w0.135: J5.B37 257.83,5.8 257.48,6.15 257.48,9.79 257.27,10.99 256.66,11.85 244.87,20.11 209.73,26.31 202.69,31.23 198.67,36.99 179.05,50.72 138.71,57.83 v8(130.51,57.83) 127.73,57.83 116.23,69.33 116.23,79.89 116.29,80.19 116.49,80.49 117.53,81.97 118.47,82.63 119.09,82.74 119.72,82.74
PE_CPU_TX_DP<6>: length 184.3
  BOTTOM w0.089: 119.36,83.97 119.42,84.02 120.04,84.02 120.43,84.41 121.59,84.41 U1.AD10
  BOTTOM w0.135: 119.36,83.97 118.51,83.97 118.36,83.94 118.37,83.94 118.22,83.91 116.65,82.82 116.49,82.59 115.03,80.51 115.03,68.83 127.23,56.63 v8(131.52,56.63) 138.6,56.63 178.58,49.58 197.81,36.12 201.89,30.29 209.13,25.19 241.74,19.44 252.68,11.78 253.3,10.89 253.48,9.89 253.48,6.15 253.83,5.8 J5.B41
PE_CPU_TX_DP<7>: length 184.2
  BOTTOM w0.089: 118.88,85.14 118.9,85.14 118.96,85.19 121.5,85.19 121.87,85.56 U1.AD11
  BOTTOM w0.135: J5.B45 249.83,5.8 249.48,6.15 249.48,10.3 249.35,11.02 248.83,11.77 238.9,18.72 208.67,24.05 201.05,29.38 196.94,35.26 178.17,48.39 138.28,55.43 v8(128.45,55.43) 126.73,55.43 113.83,68.33 113.83,81.22 113.89,81.52 115.5,83.82 116.49,84.52 117.25,85.05 117.75,85.14 118.88,85.14
PE_CPU_TX_DP<8>: length 183.1
  BOTTOM w0.089: U1.AD13 121.44,86.81 121.34,86.81 121,86.81 120.99,86.82 119.31,86.82 118.88,86.39 118.5,86.39 118.44,86.34 118.42,86.34
  BOTTOM w0.135: 118.42,86.34 117.08,86.34 116.61,86.14 116.49,86.06 114.7,84.8 112.63,81.85 112.63,67.78 126.19,54.23 v8(126.87,54.23) 138.18,54.23 177.7,47.26 196.08,34.39 200.19,28.52 208.2,22.91 234.52,18.27 243.64,11.89 244.24,11.04 244.48,9.66 244.48,6.15 244.83,5.8 J5.B50
PE_CPU_TX_DP<9>: length 182.9
  BOTTOM w0.089: U1.AD14 121.56,87.59 119.53,87.59 119.38,87.74 118.99,87.74 118.93,87.69
  BOTTOM w0.135: 118.93,87.69 117.52,87.69 116.49,87.51 116.31,87.47 113.91,85.79 112.5,84.38 111.5,82.95 111.43,82.55 111.43,67.28 125.69,53.02 v8(127.97,53.02) 138.06,53.02 177.23,46.12 195.22,33.53 199.33,27.66 207.73,21.78 231.43,17.6 239.86,11.7 240.35,10.99 240.48,10.27 240.48,6.15 240.83,5.8 J5.B54
PE_CPU_TX_DP<10>: length 186.8
  BOTTOM w0.089: U1.AD16 122.08,89.54 121.39,89.21 121.07,89.21 121.03,89.25 119.73,89.25 119.43,88.95 118.88,88.95 118.82,88.89 118.8,88.89
  BOTTOM w0.135: J5.B58 236.83,5.8 236.48,6.15 236.48,9.63 236.24,10.98 235.6,11.89 231.9,14.49 231.38,14.4 231.27,14.24 231.01,14.19 230.79,14.35 230.75,14.61 230.86,14.77 230.77,15.28 230.34,15.58 229.83,15.49 229.72,15.33 229.46,15.28 229.24,15.43 229.19,15.69 229.3,15.85 229.21,16.37 228.45,16.9 207.25,20.64 198.47,26.79 194.36,32.66 176.76,44.98 137.98,51.82 v8(128.93,51.82) 125.19,51.82 115.87,61.14 115.74,61.14 115.61,61.14 115.35,61.14 115.07,60.86 114.81,60.86 114.62,61.05 114.62,61.32 114.9,61.6 114.9,62.12 114.53,62.48 114.01,62.48 113.73,62.2 113.47,62.2 113.28,62.39 113.28,62.66 113.56,62.94 113.56,63.46 110.23,66.78 110.23,83.05 110.73,84.26 111.09,84.77 112.95,86.63 115.95,88.73 116.49,88.83 116.87,88.89 118.8,88.89
PE_CPU_TX_DP<11>: length 188.2
  BOTTOM w0.089: 118.85,90.37 118.87,90.37 118.93,90.42 119.46,90.42 119.89,89.99 121.34,89.99 121.35,90 U1.AD17
  BOTTOM w0.135: J5.B62 232.83,5.8 232.48,6.15 232.48,10.25 232.38,10.82 231.95,11.43 228.14,14.1 228.14,14.1 226.18,15.47 226.18,15.47 225.62,15.86 225.62,15.86 225.07,16.25 224.45,16.36 206.33,19.55 201.85,22.69 197.37,25.83 193.05,32 176.08,43.88 140.87,50.09 v8(126.14,50.09) 125.11,50.09 116.63,58.57 116.61,58.59 115.91,59.08 107.85,60.5 106.94,61.14 106.31,62.04 106.22,62.51 106.22,65.39 108.03,67.97 108.62,71.31 108.62,83.08 109.69,85.02 109.69,85.02 110.89,86.74 115.93,90.27 116.49,90.37 116.5,90.37 118.85,90.37 118.85,90.37
PE_CPU_TX_DP<12>: length 188.6
  BOTTOM w0.089: U1.AD19 121.46,91.52 119.16,91.52 118.9,91.78 118.5,91.78 118.44,91.73 118.42,91.73
  BOTTOM w0.135: 118.42,91.73 115.22,91.73 115.06,91.7 110.37,88.41 107.42,84.2 107.42,71.88 106.84,68.59 105.02,65.99 105.02,62.01 105.16,61.21 106.2,59.73 107.05,59.13 112.87,58.11 113.38,58 114.62,57.15 114.69,57.08 122.89,48.89 v8(124.89,48.89) 140.47,48.89 175.71,42.67 192.19,31.13 196.51,24.96 205.87,18.41 222.54,15.47 227.84,11.75 228.26,11.16 228.48,9.91 228.48,6.15 228.83,5.8 J5.B66
PE_CPU_TX_DP<13>: length 188.4
  BOTTOM w0.089: U1.AD20 121.37,92.39 119.86,92.39 119.23,93.03 119.01,93.03 118.95,92.97 118.93,92.97
  BOTTOM w0.135: J5.B70 224.83,5.8 224.48,6.15 224.48,9.94 224.34,10.74 223.64,11.73 219.32,14.76 205.51,17.19 195.3,24.34 190.98,30.51 175.23,41.54 140.36,47.69 v8(123.7,47.69) 122.39,47.69 114.58,55.5 112.79,56.74 106.61,57.84 105.32,58.74 104,60.62 103.82,61.63 103.82,66.93 105.69,69.61 106.22,72.59 106.22,84.48 106.34,85.16 108.95,88.89 114.78,92.97 118.93,92.97
PE_CPU_TX_DP<14>: length 188.6
  BOTTOM w0.089: U1.AD22 121.87,94.36 121.52,94.01 118.98,94.01 118.92,93.95 118.9,93.95
  BOTTOM w0.135: 118.9,93.95 118.27,93.95 117.83,94.39 114.71,94.39 108.03,89.71 105.05,85.45 105.02,85.28 105.02,72.95 104.53,70.19 102.41,67.17 102.41,61.93 102.76,60 104.36,57.71 106.2,56.42 111.66,55.46 113.1,54.45 113.58,54.11 113.6,54.09 121.34,46.36 v8(122.33,46.36) 140.97,46.36 174.76,40.4 190.12,29.65 194.54,23.33 204.89,16.08 216.47,14.04 219.93,11.62 220.35,11.02 220.48,10.28 220.48,6.15 220.83,5.8 J5.B74
PE_CPU_TX_DP<15>: length 188.3
  BOTTOM w0.089: U1.AD23 121.87,95.16 121.5,94.79 119.99,94.79 119.35,95.44 119.27,95.44 119.25,95.45
  BOTTOM w0.135: 119.25,95.45 119.02,95.68 114.44,95.68 114.22,95.64 107.12,90.67 103.82,85.96 103.82,85.96 103.82,73.33 103.34,70.63 102.14,68.91 101.21,67.59 101.21,60.46 101.38,59.49 103.16,56.96 105.5,55.32 110.9,54.37 112.97,52.92 120.73,45.16 v8(123.98,45.16) 140.87,45.16 173.06,39.48 187.63,29.28 191.19,24.2 204.4,14.95 213.02,13.43 215.85,11.45 216.3,10.81 216.48,9.77 216.48,5.9 216.83,5.55 J5.B78
PE_SLOT1_PRES_N: length 102
  TOP w0.114: J1.B81 213.83,40.64 211.06,43.41 202.62,43.41 172.87,73.15 129.97,73.15 128.73,74.4 R44.2
PE_SLOT1_RX_DN<0>: length 162
  IN2 w0.089: v5(138.49,85.16) 138.67,85.34 140.24,85.34 140.32,85.27 140.77,85.27 140.84,85.34 141.24,85.34 141.53,85.64 141.61,85.64 141.68,85.64 141.96,85.91 141.96,85.99 141.96,85.99 141.96,86.06 142.37,86.48 143.16,86.48 143.21,86.43 143.23,86.43
  IN2 w0.145: J1.A17 278.2,34.51 278.4,34.44 278.54,34.52 278.69,34.67 278.69,38.11 277.65,39.15 277.65,40.65 277.34,41.09 277.34,41.09 276.05,42.93 275.75,44.63 274.73,46.09 272.3,47.79 272.1,47.76 271.54,48.16 271.5,48.35 271.03,48.68 270.87,48.65 270.26,49.08 270.23,49.24 269.76,49.57 269.54,49.53 269,49.91 268.96,50.13 255.75,59.38 196.38,69.84 192.36,72.66 192.23,72.64 191.63,73.06 191.61,73.19 191.13,73.52 191,73.5 190.4,73.92 190.38,74.05 189.9,74.38 189.73,74.35 189.18,74.74 189.15,74.91 188.09,75.65 161.52,80.34 160.47,81.07 160.39,81.05 159.76,81.49 159.74,81.58 159.27,81.91 159.17,81.9 158.55,82.33 158.53,82.43 158.06,82.76 157.92,82.73 157.35,83.13 157.33,83.27 156.85,83.6 156.71,83.58 156.15,83.97 156.12,84.12 154.95,84.94 152.29,85.4 152.17,85.32 151.51,85.44 151.42,85.56 150.85,85.66 150.72,85.57 150.08,85.68 149.99,85.81 149.42,85.91 149.29,85.82 148.65,85.93 148.56,86.06 147.99,86.16 147.85,86.07 147.22,86.18 147.13,86.32 146.46,86.43 145.67,86.43 145.54,86.3 145.06,86.3 144.93,86.43 144.48,86.43 144.35,86.3 143.87,86.3 143.74,86.43 143.23,86.43
  BOTTOM w0.135: U1.D11 v5(138.49,85.16)
PE_SLOT1_RX_DN<1>: length 159.7
  IN2 w0.089: 143.28,84.42 143.26,84.42 143.22,84.47 142.09,84.47 142,84.38 141.6,84.38 141.51,84.47 141.15,84.47 141.06,84.38 140.66,84.38 140.57,84.47 140,84.47 139.72,84.75 139.02,84.75 138.82,84.54 138.67,84.54 v5(138.49,84.36)
  IN2 w0.145: 143.28,84.42 144.61,84.42 145.63,84.24 145.69,84.15 146.42,84.02 146.51,84.09 147.08,83.99 147.17,83.87 147.85,83.75 147.97,83.83 148.54,83.73 148.62,83.61 149.32,83.49 149.43,83.57 150,83.47 150.09,83.35 150.77,83.23 150.89,83.31 151.46,83.21 151.52,83.13 152.26,82.99 152.35,83.06 153.81,82.8 153.81,82.8 155.27,82.54 155.27,82.54 155.88,82.44 160,79.55 186.85,74.82 188.13,73.92 188.13,73.92 189.25,73.13 195.5,68.76 198.26,68.27 254.02,58.45 260.51,53.91 260.54,53.7 261.09,53.32 261.29,53.36 261.77,53.02 261.8,52.83 262.35,52.44 262.55,52.48 263.02,52.14 263.05,51.98 263.64,51.57 263.81,51.6 264.28,51.26 264.31,51.08 264.89,50.68 265.06,50.71 267.79,48.81 267.84,48.54 267.22,47.66 267.31,47.17 267.72,46.88 268.21,46.97 268.83,47.85 269.09,47.89 270.38,47 271.83,44.92 272.33,42.08 273.69,40.14 273.69,39.33 272.69,38.33 272.69,34.55 272.95,34.29 273.14,34.2 273.15,34.18 273.21,34.02 J1.A22
  BOTTOM w0.135: U1.D10 v5(138.49,84.36)
PE_SLOT1_RX_DN<2>: length 152.8
  IN2 w0.089: 143.28,82.9 143.26,82.9 143.22,82.94 142.64,82.94 142.39,83.19 141.8,83.19 141.7,83.08 141.34,83.08 141.24,83.19 140.89,83.19 140.78,83.08 140.43,83.08 140.33,83.19 139.96,83.19 139.71,82.94 138.67,82.94 v5(138.49,82.76)
  IN2 w0.145: J1.A26 269.21,34.02 269.15,34.18 269.14,34.2 268.95,34.29 268.69,34.55 268.69,38.27 269.67,39.26 269.67,40.67 267.71,43.47 267.44,45 266.92,45.74 266.74,45.77 266.33,46.37 266.36,46.54 266.02,47.02 265.88,47.04 265.44,47.67 265.46,47.82 264.93,48.58 251.99,57.64 198.26,67.11 194.06,67.85 185.62,73.76 159.38,78.39 154.92,81.52 153.6,81.75 153.45,81.64 152.79,81.76 152.68,81.91 152.11,82.01 151.98,81.92 151.28,82.04 151.19,82.17 150.62,82.27 150.5,82.19 149.78,82.32 149.7,82.44 149.13,82.54 148.99,82.44 148.3,82.56 148.21,82.7 147.64,82.8 147.51,82.71 146.8,82.84 146.72,82.96 145.94,83.1 143.78,82.9 143.28,82.9
  BOTTOM w0.135: U1.D8 v5(138.49,82.76)
PE_SLOT1_RX_DN<3>: length 152.1
  IN2 w0.089: v5(138.49,81.96) 138.67,82.14 138.82,82.14 139.02,82.35 139.75,82.35 139.83,82.27 140.31,82.27 140.39,82.35 140.79,82.35 141.43,82.23 141.49,82.15 142.09,82.05 142.17,82.1 142.72,82.01 143.22,82.01 143.26,81.96 143.28,81.96
  IN2 w0.145: J1.A30 265.21,34.02 265.15,34.18 265.14,34.2 264.95,34.29 264.69,34.55 264.69,38.15 263.69,39.14 263.69,40.34 263.44,41.78 263.15,42.2 262.56,45.5 262.56,45.51 261.18,47.48 260.92,47.52 260.39,47.15 259.96,47.23 259.61,47.71 259.69,48.14 260.22,48.52 260.27,48.78 260.11,49 259.85,49.05 258.96,48.43 258.46,48.51 258.17,48.93 258.26,49.42 259.15,50.04 259.2,50.31 258.65,51.09 256.77,52.41 256.52,52.36 256.14,52.63 256.09,52.89 255.7,53.16 255.45,53.11 255.07,53.38 255.02,53.63 250.66,56.69 240.86,58.42 198.26,65.92 198.21,65.93 193.56,66.92 193.5,66.93 185.27,72.69 159.14,77.3 154.63,80.46 153.2,80.71 153.02,80.59 152.21,80.73 152.09,80.91 151.52,81.01 151.37,80.91 150.51,81.06 150.41,81.2 149.84,81.3 149.69,81.2 148.83,81.35 148.73,81.5 148.16,81.6 148.01,81.5 147.15,81.65 147.05,81.8 146.1,81.96 143.28,81.96
  BOTTOM w0.135: U1.D7 v5(138.49,81.96)
PE_SLOT1_RX_DN<4>: length 143.1
  IN2 w0.089: v5(138.49,80.36) 138.67,80.54 139.35,80.54 140.18,80.69 140.82,80.69 140.86,80.64 140.91,80.59 141.27,80.59 141.32,80.64 141.36,80.69 141.72,80.69 141.77,80.64 141.81,80.59 142.17,80.59 142.22,80.64 142.26,80.69 142.87,80.69 142.91,80.64 142.94,80.64
  IN2 w0.145: 142.94,80.64 145.35,80.64 146.24,80.49 146.29,80.41 147.04,80.27 147.12,80.33 147.69,80.23 147.75,80.15 148.49,80.02 148.58,80.08 149.15,79.97 149.2,79.9 149.96,79.77 150.03,79.82 150.6,79.72 150.65,79.65 151.41,79.51 151.49,79.56 152.06,79.46 152.1,79.4 152.88,79.26 152.94,79.3 154.3,79.07 158.4,76.2 184.88,71.53 193.37,65.59 198.26,64.72 236.18,58.03 247.9,55.97 252.08,53.04 253.38,51.19 253.35,51.02 253.67,50.55 253.85,50.52 254.13,50.12 254.1,49.97 254.44,49.48 254.6,49.45 254.87,49.05 254.84,48.88 255.17,48.41 255.34,48.38 255.62,47.98 255.59,47.79 255.9,47.35 256.09,47.31 257.23,45.7 257.61,43.52 258.19,42.7 258.43,42.46 259.61,40.77 259.69,40.31 259.69,39.36 258.69,38.35 258.69,34.55 258.95,34.29 259.14,34.2 259.15,34.18 259.21,34.02 J1.A36
  BOTTOM w0.135: U1.D5 v5(138.49,80.36)
PE_SLOT1_RX_DN<5>: length 141.7
  IN2 w0.089: 142.68,79.62 142.65,79.62 142.61,79.67 142.14,79.67 141.86,79.95 141.5,79.95 141.43,79.88 140.91,79.88 140.85,79.95 140.46,79.95 140.39,79.88 139.87,79.88 139.81,79.95 139.02,79.95 138.82,79.74 138.67,79.74 v5(138.49,79.56)
  IN2 w0.145: 142.68,79.62 145.2,79.62 146.03,79.48 146.11,79.35 146.89,79.22 147.02,79.3 147.59,79.2 147.65,79.11 148.49,78.97 148.58,79.03 149.15,78.93 149.21,78.84 150.05,78.69 150.14,78.75 150.71,78.65 150.79,78.54 151.6,78.4 151.7,78.48 153.32,78.19 154.76,77.19 154.8,76.92 154.28,76.18 154.37,75.68 154.78,75.4 155.28,75.48 155.8,76.23 156.06,76.27 157.99,74.92 184.19,70.3 192.25,64.66 245.04,55.35 245.98,54.69 246.02,54.48 246.43,54.19 246.64,54.23 247.05,53.94 247.09,53.74 247.5,53.45 247.71,53.48 249.54,52.2 251.07,50.01 251.05,49.85 251.38,49.37 251.54,49.35 251.99,48.7 251.96,48.54 252.28,48.08 252.45,48.05 253,47.26 253.76,42.95 254.83,41.41 255.59,40.62 255.68,40.12 255.68,39.36 254.69,38.37 254.69,34.55 254.95,34.29 255.14,34.2 255.15,34.18 255.21,34.02 J1.A40
  BOTTOM w0.135: U1.D4 v5(138.49,79.56)
PE_SLOT1_RX_DN<6>: length 134.7
  IN2 w0.089: v5(138.49,77.96) 138.67,78.14 138.82,78.14 139.02,78.35 139.72,78.35 140,78.07 141.05,78.07 141.1,78.02 141.12,78.02
  IN2 w0.145: J1.A44 251.21,34.02 251.15,34.18 251.14,34.2 250.95,34.29 250.69,34.55 250.69,38.33 251.66,39.31 251.66,39.95 251.55,40.58 251.02,41.34 250.05,42.73 249.6,45.31 249.17,45.92 249.04,45.94 248.68,46.45 248.7,46.59 248.42,46.99 248.27,47.01 247.92,47.5 247.95,47.66 247.67,48.06 247.5,48.09 247.17,48.56 247.2,48.73 246.92,49.13 246.76,49.15 246.43,49.64 246.45,49.8 244.94,51.95 240.69,54.93 190.48,63.78 183.09,68.96 155.02,73.91 154.74,74.11 154.59,74.08 154.04,74.47 154.02,74.61 153.54,74.94 153.39,74.91 152.85,75.29 152.82,75.45 152.35,75.78 152.21,75.75 151.65,76.14 151.63,76.28 151.15,76.61 151.02,76.59 150.46,76.98 150.43,77.12 149.71,77.63 147.74,77.97 147.65,77.91 146.98,78.03 146.92,78.12 146.34,78.22 146.23,78.15 145.63,78.25 145.56,78.36 144.83,78.49 143.87,78.49 143.28,78.38 141.42,78.02 141.12,78.02
  BOTTOM w0.135: U1.D2 v5(138.49,77.96)
PE_SLOT1_RX_DN<7>: length 132.3
  IN2 w0.089: v5(138.49,77.16) 138.67,77.34 139.29,77.34 139.38,77.26 139.82,77.26 139.9,77.34 140.7,77.34 140.74,77.3 140.77,77.3
  IN2 w0.145: 140.77,77.3 141.51,77.3 141.59,77.22 142.18,77.22 142.27,77.3 143.03,77.3 143.11,77.22 143.94,77.22 144.02,77.3 145,77.3 145.72,77.17 145.8,77.06 146.48,76.94 146.59,77.02 147.16,76.92 147.22,76.83 147.93,76.7 148.02,76.77 148.94,76.6 151.14,75.07 151.18,74.8 150.57,73.92 150.65,73.42 151.06,73.14 151.56,73.22 152.18,74.11 152.44,74.15 154.7,72.57 182.69,67.64 189.54,62.84 235.86,54.67 235.9,54.61 237.02,54.42 237.08,54.46 238,54.3 239.29,53.4 239.3,53.3 239.94,52.85 240.04,52.87 241.53,51.83 242.15,50.94 242.33,49.91 242.25,49.79 242.35,49.2 242.47,49.11 242.56,48.62 242.48,48.51 242.59,47.91 242.7,47.83 242.79,47.34 242.74,47.27 242.86,46.59 242.93,46.54 243.25,44.73 243.93,43.76 243.9,43.58 244.18,43.17 244.36,43.14 244.62,42.77 244.59,42.59 244.87,42.19 245.05,42.15 245.62,41.34 245.74,40.67 245.74,39.06 246.69,38.11 246.69,34.55 246.95,34.29 247.14,34.2 247.15,34.18 247.21,34.02 J1.A48
  BOTTOM w0.135: U1.D1 v5(138.49,77.16)
PE_SLOT1_RX_DN<8>: length 129.2
  IN2 w0.089: v5(135.29,79.56) 135.47,79.38 135.47,77.88 135.43,77.83 135.38,77.78 135.38,77.39 135.43,77.34 135.47,77.3 135.47,76.75 135.43,76.7 135.43,76.68
  IN2 w0.145: J1.A53 242.2,34.51 242.4,34.44 242.54,34.52 242.67,34.65 242.67,38.26 241.69,39.25 241.69,40.87 240.28,42.88 240.11,42.91 239.82,43.32 239.85,43.49 239.59,43.86 239.42,43.89 239.13,44.3 239.16,44.47 237.56,46.76 225.22,55.4 189.1,61.77 182.12,66.66 155.38,71.37 155.38,71.37 155.25,71.28 154.64,71.39 154.55,71.52 154.09,71.6 154.09,71.6 153.96,71.51 153.35,71.61 153.26,71.75 152.81,71.83 152.81,71.82 152.68,71.74 152.06,71.85 151.97,71.97 150.81,72.18 149.66,72.98 149.5,72.95 149.03,73.28 149,73.44 148.59,73.73 148.46,73.71 147.96,74.06 147.93,74.19 147.52,74.48 147.4,74.46 146.89,74.82 146.86,74.94 146.3,75.33 144.84,75.59 144.72,75.51 144.11,75.62 144.03,75.73 143.55,75.82 143.45,75.75 143.28,75.78 142.81,75.86 142.74,75.96 142.27,76.05 142.15,75.96 141.54,76.07 141.45,76.19 140.53,76.35 140.17,76.35 139.64,75.82 135.83,75.82 135.43,76.22 135.43,76.68
  BOTTOM w0.135: U1.H4 v5(135.29,79.56)
PE_SLOT1_RX_DN<9>: length 126.8
  IN2 w0.089: v5(134.49,79.56) 134.67,79.38 134.67,79.17 134.91,78.93 134.91,78.26 134.55,77.9 134.49,77.9 134.48,77.88
  IN2 w0.145: 134.48,77.88 134.15,77.56 134.15,77.29 134.05,77.19 134.05,76.62 134.15,76.52 134.15,76.22 134.45,75.92 134.45,75.78 134.86,75.37 135.01,75.37 135.93,74.45 141.04,74.45 142.13,74.25 142.19,74.16 142.92,74.03 143.02,74.1 143.59,74 143.64,73.93 144.41,73.79 144.48,73.84 145.05,73.74 145.11,73.65 145.85,73.52 145.94,73.58 146.3,73.52 146.89,73.1 146.91,72.99 147.52,72.56 147.63,72.58 148.11,72.25 148.13,72.13 148.74,71.71 148.85,71.73 150,70.92 181.71,65.33 182.63,64.69 182.65,64.57 183.25,64.15 183.37,64.17 183.85,63.84 183.87,63.7 184.46,63.29 184.59,63.31 185.07,62.98 185.09,62.86 185.7,62.44 185.81,62.46 186.29,62.13 186.31,61.98 186.88,61.58 187.03,61.6 188.12,60.84 223.35,54.63 231.04,49.24 233.46,46.82 235.17,44.38 235.49,43.89 235.45,43.72 235.74,43.28 235.9,43.25 236.15,42.87 236.11,42.7 236.4,42.26 236.57,42.23 237.69,40.49 237.69,39.22 238.69,38.23 238.69,34.66 238.54,34.52 238.4,34.45 238.4,34.44 238.2,34.51 J1.A57
  BOTTOM w0.135: U1.J4 v5(134.49,79.56)
PE_SLOT1_RX_DN<10>: length 125.5
  IN2 w0.089: v5(132.89,79.56) 133.07,79.38 133.07,78.02 132.5,77.45 132.5,76.7 132.45,76.66 132.45,76.64
  IN2 w0.145: 132.45,76.64 132.45,75.68 132.81,75.32 132.81,75.11 133.17,74.75 133.38,74.75 133.55,74.57 133.79,73.23 134.12,72.75 135.26,71.95 137.02,71.64 137.11,71.51 137.89,71.37 138.02,71.47 138.59,71.37 138.68,71.24 139.47,71.1 139.6,71.19 140.17,71.09 140.25,70.98 141.06,70.83 141.17,70.91 141.74,70.81 141.81,70.71 142.64,70.56 142.74,70.64 143.31,70.53 143.42,70.38 144.16,70.25 144.32,70.36 144.92,70.25 145.02,70.11 145.71,69.99 145.86,70.09 180.91,63.9 186.11,60.27 186.11,60.27 221.13,54.09 224.96,51.41 225,51.2 225.37,50.94 225.58,50.98 225.94,50.72 225.98,50.51 226.35,50.25 226.56,50.29 227.6,49.56 230.48,45.45 230.48,45.45 231.16,44.47 231.13,44.31 231.43,43.89 231.59,43.86 233.61,40.97 233.71,40.39 233.71,39.2 234.69,38.23 234.69,34.67 234.54,34.52 234.4,34.44 234.2,34.51 J1.A61
  BOTTOM w0.135: U1.L4 v5(132.89,79.56)
PE_SLOT1_RX_DN<11>: length 123.6
  IN2 w0.089: 131.63,76.74 131.63,76.76 131.67,76.8 131.67,77.71 132.55,78.59 132.55,78.89 132.27,79.17 132.27,79.38 v5(132.09,79.56)
  IN2 w0.145: J1.A65 230.2,34.51 230.4,34.44 230.54,34.52 230.68,34.66 230.68,38.24 229.69,39.24 229.69,39.97 229.45,41.32 226.76,45.16 226.76,45.16 226.6,45.18 226.29,45.63 226.32,45.79 226.06,46.16 225.9,46.19 225.59,46.63 225.62,46.79 222.19,51.68 219.43,53.44 184.52,59.6 179.65,63.01 178.07,63.29 178.07,63.29 176.52,63.56 174.98,63.83 174.87,63.75 174.09,63.89 174.01,64 173.44,64.1 173.31,64.01 172.55,64.15 172.46,64.27 171.89,64.37 171.78,64.3 170.99,64.44 170.92,64.55 170.35,64.65 170.25,64.58 169.45,64.72 169.37,64.82 168.8,64.92 168.71,64.85 167.9,65 167.83,65.09 143.58,69.37 143.45,69.28 142.77,69.4 142.68,69.52 142.11,69.63 141.99,69.54 141.29,69.67 141.21,69.78 140.64,69.89 140.49,69.78 139.84,69.9 139.74,70.04 139.17,70.14 139.02,70.04 138.37,70.16 138.26,70.3 137.69,70.4 137.58,70.32 136.88,70.44 136.79,70.56 134.92,70.89 132.82,72.36 132.4,72.97 132.17,74.27 131.63,74.81 131.63,76.74
  BOTTOM w0.135: U1.M4 v5(132.09,79.56)
PE_SLOT1_RX_DN<12>: length 123.1
  IN2 w0.089: 130.07,77.23 130.07,77.25 130.11,77.29 130.11,77.8 129.87,78.04 129.87,79.38 v5(129.69,79.56)
  IN2 w0.145: J1.A69 226.2,34.51 226.4,34.44 226.54,34.52 226.68,34.66 226.68,38.24 225.7,39.22 225.7,40.35 225.54,41.27 224.3,43.04 224.18,43.72 224.09,43.79 223.96,44.53 224.02,44.62 223.81,45.84 223.46,46.34 223.27,46.38 223.02,46.74 223.05,46.92 222.82,47.25 222.66,47.28 222.39,47.66 222.42,47.83 220.5,50.57 217.48,52.68 214.53,53.2 214.39,53.11 213.9,53.19 213.81,53.32 213.42,53.39 213.29,53.3 212.79,53.39 212.7,53.52 211.87,53.67 211.05,53.81 210.92,53.72 210.43,53.81 210.34,53.94 209.94,54.01 209.81,53.91 209.32,54 209.23,54.13 200.72,55.63 191.62,54.03 144.51,62.33 134.26,69.51 133.86,69.91 133.68,69.91 133.3,70.29 133.3,70.47 131.9,71.87 131.73,71.87 131.35,72.25 131.35,72.42 130.67,73.1 130.67,74.75 130.07,75.35 130.07,75.91 129.97,76.01 129.87,76.1 129.87,76.55 129.97,76.65 130.07,76.75 130.07,77.23
  BOTTOM w0.135: U1.P4 v5(129.69,79.56)
